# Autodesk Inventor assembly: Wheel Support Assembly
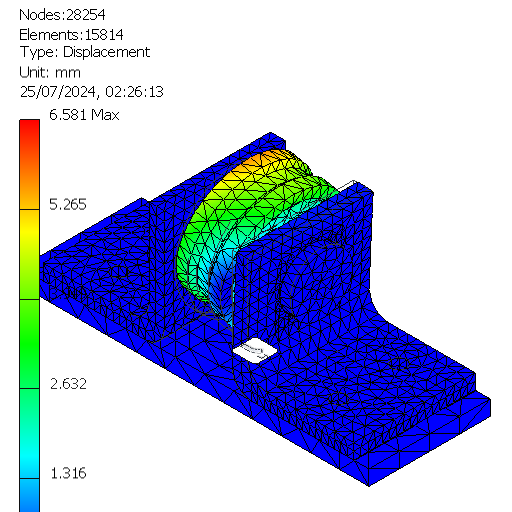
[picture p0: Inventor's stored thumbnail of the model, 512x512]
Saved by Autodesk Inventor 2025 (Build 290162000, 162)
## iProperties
Created: 2016-08
Part Number: Wheel Support Assembly
Document SubType Name: Assembly
Designer: Sandeep
Mass: 455.912 g
Surface Area: 326.65 cm^2
Volume: 63.7639 cm^3
Density: 7.15 g/cm^3
Author: Sandeep
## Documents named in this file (5)
- D:\CAD\Inventor\Autodesk Inventor 2025\Resources\2025\c15_Inv_2025_tut\c15_tut03_inv\Wheel Support Assembly.iam
- D:\CAD\Inventor\Autodesk Inventor 2025\Resources\2025\c15_Inv_2025_tut\c15_tut03_inv\base.ipt
- D:\CAD\Inventor\Autodesk Inventor 2025\Resources\2025\c15_Inv_2025_tut\c15_tut03_inv\Support.ipt
- D:\CAD\Inventor\Autodesk Inventor 2025\Resources\2025\c15_Inv_2025_tut\c15_tut03_inv\Wheel.ipt
- D:\CAD\Inventor\Autodesk Inventor 2025\Resources\2025\c15_Inv_2025_tut\c15_tut03_inv\Shoulder screw.ipt
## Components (5 placed, 4 different names)
1. base:1 — Insert:1, Mate:1, Insert:2, Mate:2
2. Support:1 — Insert:1, Mate:1, Insert:3
3. Support:2 — Insert:2, Mate:2, Mate:3, Mate:4
4. Wheel:1 — Insert:3
5. Shoulder screw:1 — Mate:3, Mate:4
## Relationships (7: Mate 4, Insert 3)
- Insert:1: base:1 ↔ Support:1
- Mate:1: base:1 ↔ Support:1
- Insert:2: base:1 ↔ Support:2
- Mate:2: base:1 ↔ Support:2
- Insert:3: Support:1 ↔ Wheel:1
- Mate:3: Support:2 ↔ Shoulder screw:1
- Mate:4: Support:2 ↔ Shoulder screw:1
## Named parameters: sa_0 = 50 deg, sa_1 = 0, sa_2 = 0, sa_3 = 0
